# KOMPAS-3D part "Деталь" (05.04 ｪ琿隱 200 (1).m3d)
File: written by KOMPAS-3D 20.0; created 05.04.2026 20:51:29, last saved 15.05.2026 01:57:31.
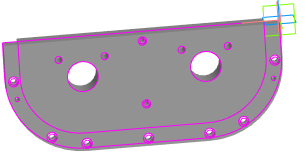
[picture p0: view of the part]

Document properties: Автор: taras; Полное имя файла: E:\test_kompas\all_v18\05.04 крышка200 (1).m3d

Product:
- Part/product: Деталь
    Масса: 19.9484
  - Body: Тело 22
  - Body: Тело 21
  - Body: Тело 20
  - Body: Тело 19

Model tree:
1. Эскиз:3
2. Элемент выдавливания:24
     Расстояние 1 = 20
3. Элемент выдавливания:25
     Расстояние 1 = -20
4. Эскиз:4  (with: Элемент выдавливания:24)
5. Элемент выдавливания:26
     Расстояние 1 = -40
6. Элемент выдавливания:27
     Расстояние 1 = -40
7. Элемент выдавливания:28
     Расстояние 2 = 40
8. Элемент выдавливания:29
     Расстояние 2 = 11
9. Элемент выдавливания:30
     Расстояние 2 = 20
10. Элемент выдавливания:31
     Расстояние 2 = 20
11. Элемент выдавливания:32
     Расстояние 2 = 30
12. Элемент выдавливания:35
     Расстояние 2 = 20
13. Элемент выдавливания:36
     Расстояние 2 = 10
14. Элемент выдавливания:37
     Расстояние 2 = 40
